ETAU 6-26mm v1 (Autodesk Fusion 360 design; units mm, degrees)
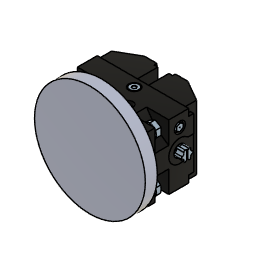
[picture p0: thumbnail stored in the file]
parameter "Ouverture" = 20
base_feature "Base Feature1" OffsetX 0 OffsetY 0 OffsetZ 0
joint_origin "JointOrigin1" OffsetX 0 OffsetY 0 OffsetZ 0
base_feature "Base Feature1"
joint_origin "JointOrigin1" OffsetX 0 OffsetY 0 OffsetZ 0
joint_origin "JointOrigin2" OffsetX 0 OffsetY 0 OffsetZ 0
base_feature "Base Feature1"
joint "Assemble1" alignOffsetX 0 alignOffsetY 0 alignOffsetZ -6 (= "-Ouverture / 2 + 4 mm")
joint "Assemble2" alignOffsetX 0 alignOffsetY 0 alignOffsetZ 6 (= "Ouverture / 2 - 4 mm")
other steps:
create_component "CreateComponent1"
create_component "CreateComponent2"
create_component "CreateComponent3"
joint_origin "JointOrigin3" OffsetX 0 OffsetY 0 OffsetZ 0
